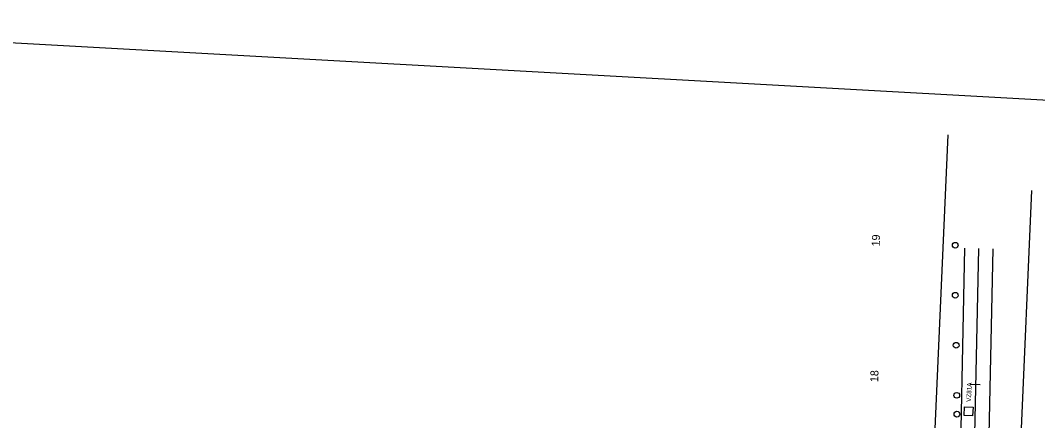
# Model space of a CAD drawing. Extents: x 0 to 1361828, y 0 to 1470398.
# Drawn here: x 682944 to 683656, y 735278 to 735558 of the extents above; entities that cross this region are included whole.
import ezdxf

# ---------------------------------------------------------------- set-up
doc = ezdxf.new("R2010")
doc.units = 0
for name, color, linetype in [('$', 7, 'Continuous'), ('border All Plan 20-40_Border 3 - Level 1', 7, 'Continuous'), ('MOT Stage 1', 7, 'Continuous'), ('MOT Stage 1 Lanes', 7, 'Continuous'), ('R_Horz Alg Station', 7, 'Continuous'), ('RW-EX', 7, 'Continuous'), ('Video-Zones-pr', 7, 'Continuous')]:
    doc.layers.add(name, color=color, linetype=linetype)

# ---------------------------------------------------------------- blocks, each defined once
blk = doc.blocks.new('BAREL_1720')
at = {"layer": 'MOT Stage 1'}
blk.add_circle((0, 0), 2.88, dxfattribs=at)
blk = doc.blocks.new('BAREL_1721')
at = {"layer": 'MOT Stage 1'}
blk.add_circle((0, 0), 2.88, dxfattribs=at)
blk = doc.blocks.new('BAREL_1722')
at = {"layer": 'MOT Stage 1'}
blk.add_circle((0, 0), 2.88, dxfattribs=at)
blk = doc.blocks.new('BAREL_1723')
at = {"layer": 'MOT Stage 1'}
blk.add_circle((0, 0), 2.88, dxfattribs=at)
blk = doc.blocks.new('BAREL_1728')
at = {"layer": 'MOT Stage 1'}
blk.add_circle((0, 0), 2.88, dxfattribs=at)

msp = doc.modelspace()

# ---------------------------------------------------------------- linework, layer by layer
at = {"layer": 'border All Plan 20-40_Border 3 - Level 1'}
msp.add_line((682658.17, 735557.86), (684236.65, 735470.4), dxfattribs=at)
at = {"layer": 'MOT Stage 1 Lanes'}
for points in [[(683604.91, 735398.45), (683600.74, 735203.61), (683598.98, 735163.25), (683593.24, 735081.04), (683613.19, 735079.65), (683618.95, 735162.12), (683620.73, 735202.96), (683624.91, 735398.02)], [(683603.28, 735081.34), (683608.96, 735162.68), (683610.73, 735203.28), (683614.91, 735398.23)]]:
    msp.add_lwpolyline(points, dxfattribs=at)
at = {"layer": 'R_Horz Alg Station'}
msp.add_lwpolyline([(683609.11, 735303.51), (683615.77, 735303.21)], dxfattribs=at)
at = {"layer": 'RW-EX'}
for p, q in [((683579.69, 735164.78), (683593.35, 735477.74)), ((683651.72, 735438.91), (683636.35, 735086.75))]:
    msp.add_line(p, q, dxfattribs=at)
at = {"layer": 'Video-Zones-pr'}
msp.add_lwpolyline([(683610.51, 735281.32), (683604.51, 735281.58), (683604.77, 735287.58), (683610.77, 735287.32), (683610.51, 735281.32)], dxfattribs=at)

# ---------------------------------------------------------------- block references
at = {"layer": 'MOT Stage 1', "xscale": 0.6945420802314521, "yscale": 0.6945420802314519, "rotation": 87.04179557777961}
for name, p in [('BAREL_1723', (683598.35, 735400.61)), ('BAREL_1722', (683598.35, 735365.61)), ('BAREL_1721', (683598.99, 735330.62)), ('BAREL_1720', (683599.4, 735295.62)), ('BAREL_1728', (683599.54, 735282.44))]:
    msp.add_blockref(name, p, dxfattribs=at)

# ---------------------------------------------------------------- texts
at = {"layer": '$'}
for s, height, rotation, p in [('19', 5.6, 88.38872, (683545.51, 735399.68)), ('18', 5.6, 88.38872, (683544.47, 735304.79)), ('VZ81A', 3.2, 87.50059, (683609.29, 735291.01))]:
    msp.add_text(s, height=height, rotation=rotation, dxfattribs=at).set_placement(p)

doc.saveas('drawing.dxf')
